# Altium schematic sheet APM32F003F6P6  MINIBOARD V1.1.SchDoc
size A4; Organization: Altium Limited; Address1: 3 Minna Close; Address2: Belrose; Address3: NSW 2085; Address4: Australia; PageSetup: Record=PageOptions¦CenterHorizontal=True¦CenterVertical=True¦PrintScale=1.00¦XCorrection=1.00¦YCorrection=1.00¦PrintKind=0¦BorderSize=5000000¦LeftOffset=0¦BottomOffset=0¦Orientation=2¦PaperLength=1000¦PaperWidth=1000¦Scale=100¦PaperSource=7¦PrintQuality=-4¦MediaType=1¦DitherType=10¦PrintScaleMode=1¦PaperKind=A4
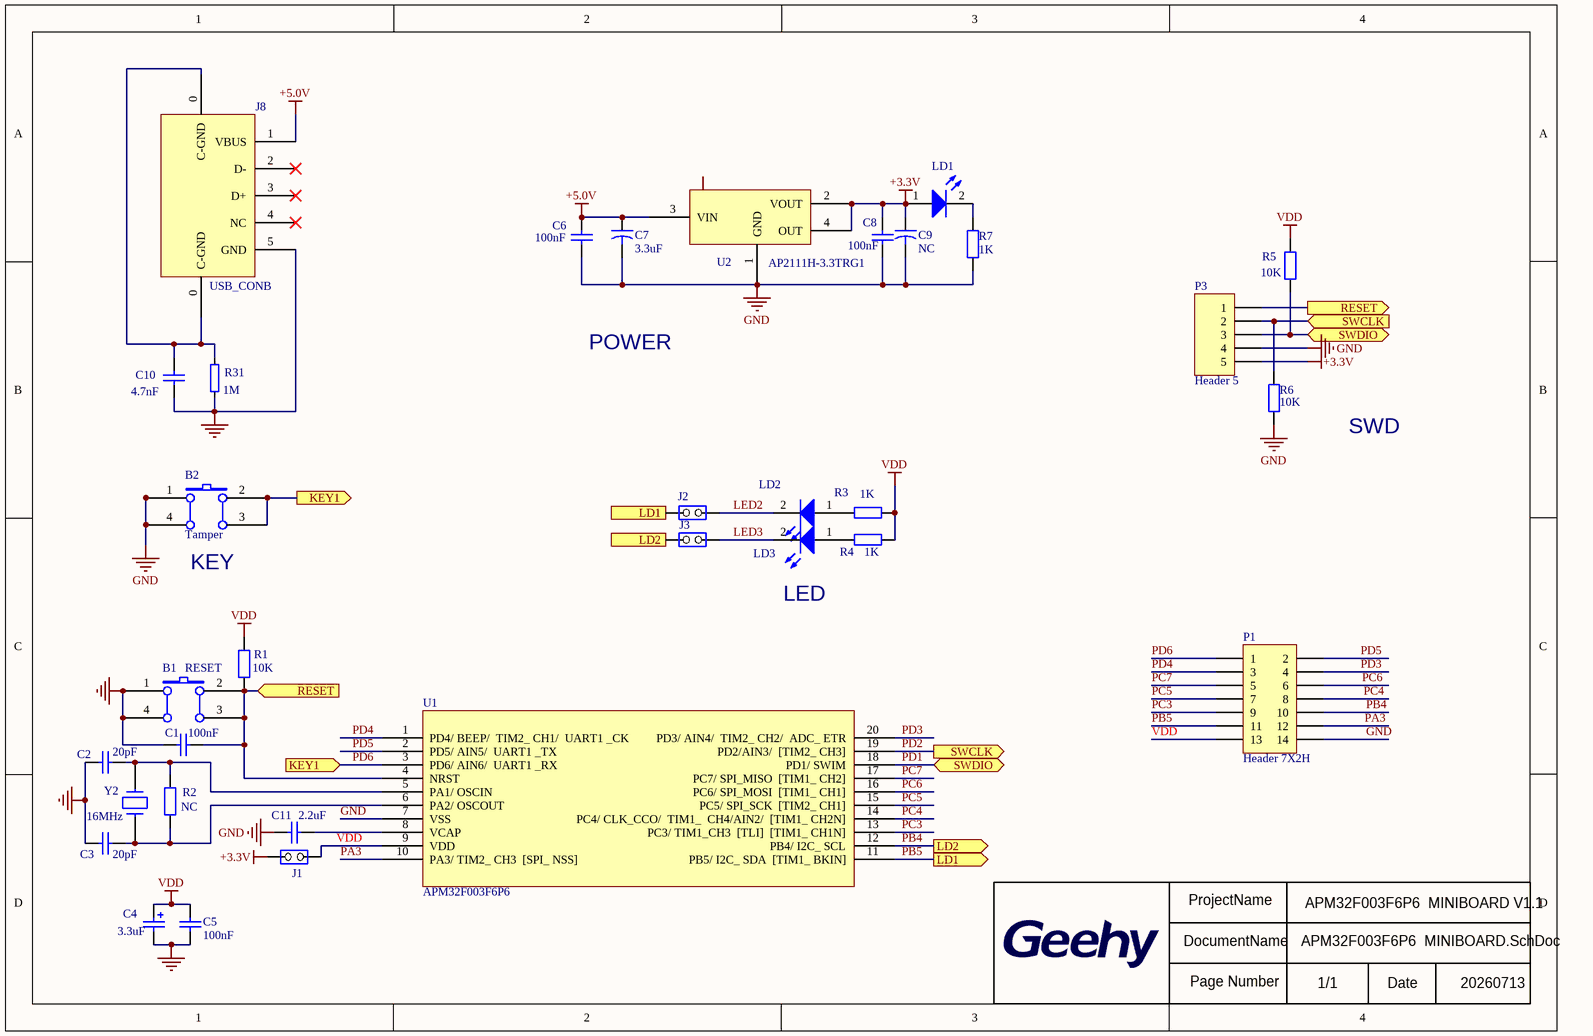
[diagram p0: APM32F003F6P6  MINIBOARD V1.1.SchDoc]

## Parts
B1  RESET  [PB10]
B2  Tamper  [PB10]
C1  100nF  [0603P]
C2  20pF  [0603P]
C3  20pF  [0603P]
C4  3.3uF  [TAN-B]
C5  100nF  [0603P]
C6  100nF  [0603P]
C7  3.3uF  [TAN-B]
C8  100nF  [0603P]
C9  NC  [TAN-B]
C10  4.7nF  [0603]
C11  2.2uF  [0603P]
J1  (no value)  [SIP2]
J2  (no value)  [SIP2]
J3  (no value)  [SIP2]
J8  USB_CONB  [MICROUSB-T]
LD1  LED  [D0603]  (value not drawn)
LD2  LED  [D0603]  (value not drawn)
LD3  LED  [D0603]  (value not drawn)
P1  Header 7X2H  [HDR2X7-T]
P3  Header 5  [HDR1X5]
R1  10K  [0603]
R2  NC  [0603]
R3  1K  [0603]
R4  1K  [0603]
R5  10K  [0603]
R6  10K  [0603]
R7  1K  [0603]
R31  1M  [0603]
U1  APM32F003F6P6  [TSSOP-20A]
U2  AP2111H-3.3TRG1  [SPX1117M]
Y2  16MHz  [XTAL-T]

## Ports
KEY1 (in), KEY1 (out), LD1 (in), LD1 (out), LD2 (in), LD2 (out), RESET (in), RESET (out), SWCLK (in), SWCLK (out), SWDIO (bidir)

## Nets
+3.3V: C8.2 C9.1 J1.2(NO) LD1.1(A) P3.5 U2.2(VOUT) U2.4(OUT)
+5.0V: C6.2 C7.1 J8.1(VBUS) U2.3(VIN)
GND: B1.1(A0) B1.4(A1) B2.1(A0) B2.4(A1) C1.1 C2.1 C3.1 C4.2 C5.2 C6.1 C7.2 C8.1 C9.2 C10.1 C11.1 J8.5(GND) P1.14 P3.4 R6.1 R7.1 R31.1 U1.7(VSS) U2.1(GND)
VDD: C4.1 C5.1 J1.1(COMMON) P1.13 R1.2 R3.1 R4.1 R5.2 U1.9(VDD)
LED2: J2.1(COMMON) LD2.2(K)
LED3: J3.1(COMMON) LD3.2(K)
PA3: P1.12 U1.10(PA3/_TIM2__CH3__[SPI__NSS])
PB4: J3.2(NO) P1.10 U1.12(PB4/_I2C__SCL) ; port LD2
PB5: J2.2(NO) P1.11 U1.11(PB5/_I2C__SDA__[TIM1__BKIN]) ; port LD1
PC3: P1.9 U1.13(PC3/_TIM1_CH3__[TLI]__[TIM1__CH1N])
PC4: P1.8 U1.14(PC4/_CLK_CCO/__TIM1___CH4/AIN2/__[TIM1__CH2N])
PC5: P1.7 U1.15(PC5/_SPI_SCK__[TIM2__CH1])
PC6: P1.6 U1.16(PC6/_SPI_MOSI__[TIM1__CH1])
PC7: P1.5 U1.17(PC7/_SPI_MISO__[TIM1__CH2])
PD1: P3.3 R5.1 U1.18(PD1/_SWIM) ; port SWDIO
PD2: P3.2 R6.2 U1.19(PD2/AIN3/__[TIM2__CH3]) ; port SWCLK
PD3: P1.4 U1.20(PD3/_AIN4/__TIM2__CH2/__ADC__ETR)
PD4: P1.3 U1.1(PD4/_BEEP/__TIM2__CH1/__UART1__CK)
PD5: P1.2 U1.2(PD5/_AIN5/__UART1__TX)
PD6: B2.2(B0) B2.3(B1) P1.1 U1.3(PD6/_AIN6/__UART1__RX) ; port KEY1
RESET: B1.2(B0) B1.3(B1) C1.2 P3.1 R1.1 U1.4(NRST) ; port RESET
NetC2_2: C2.2 R2.2 U1.5(PA1/_OSCIN) Y2.1
NetC3_2: C3.2 R2.1 U1.6(PA2/_OSCOUT) Y2.2
NetC10_2: C10.2 J8.0(C-GND) R31.2
NetC11_2: C11.2 U1.8(VCAP)
NetLD1_2: LD1.2(K) R7.2
NetLD2_1: LD2.1(A) R3.2
NetLD3_1: LD3.1(A) R4.2

Not connected (* = marked no-connect by the designer): J8 2(D-)* 3(D+)* 4(NC)*

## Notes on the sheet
- POWER
- SWD
- (near B2) KEY
- LED
- ProjectName
- APM32F003F6P6  MINIBOARD V1.1
- DocumentName
- Page Number
- APM32F003F6P6  MINIBOARD.SchDoc
- 1/1
- Date
- 20260713

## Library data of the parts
B1 B2 = SW PUSHBUTTON: SE PUSHBUTTON
C1 C10 C11 = CAP: Capacitor; Value: 100pF
C2 C3 = Cap: Capacitor
C4 = Cap Pol1: Polarized Capacitor (Radial); Value: 100pF
C5 = CAP: Capacitor
C6 C8 = Cap: Capacitor; Value: 104
C7 C9 = Cap2: Capacitor; Value: 220uF
J1-J3 = JP2
LD1-LD3 = LED2: Typical RED, GREEN, YELLOW, AMBER GaAs LED
P1 = Header 7X2H: Header, 7-Pin, Dual row, Right Angle
P3 = Header 5: Header, 5-Pin
R1 R5 R6 = Res2: Resistor
R2 = Res2: Resistor; Value: 1M
R3 R4 R7 = Res2: Resistor; Value: 470
R31 = RES: '1/8W 5%; 描述: 5%/1/10W
U1 = 003-20L
U2 = SPX1117
Y2 = CRYSTAL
